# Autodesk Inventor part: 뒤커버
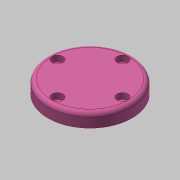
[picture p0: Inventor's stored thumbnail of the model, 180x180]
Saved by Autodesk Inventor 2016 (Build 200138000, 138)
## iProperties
Created: 2015-09
Part Number: 뒤커버
Material: 알루미늄 6061
Document SubType Name: Modeling
Designer: mduedu
Density: 1 g/cm^3
Appearance: 분홍색
Author: mduedu
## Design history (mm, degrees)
sketch "스케치1"
  geometry: L1 (0, 7.5)-(0, -7.5); L2 (0, 7.5)-(31, 7.5); L3 (31, 7.5)-(31, -2.5); L4 (31, -2.5)-(17.5, -2.5); L5 (17.5, -2.5)-(17.5, -7.5); L6 (17.5, -7.5)-(0, -7.5); 2 further points
  constraints: 12 end point, 2 parallel, 2 perpendicular, 1 coincident, 1 horizontal, 1 midpoint, 1 vertical
  dimensions: "d0" = 15 distance of L1.start L1.end; "d1" = 62 diameter of L3 L1; "d2" = 35 diameter of L5 L1; "d3" = 10 distance of L2.end L3.end
revolve "회전1" sketch "스케치1" stored, may be unused: angle "d4" = 90 deg
fillet "모깎기2" dims "d48" = 3
sketch "스케치4" dims "d49" = 48
  geometry: 3 further points
  constraints: 2 vertical alignment, 1 coincident, 2 other
hole "구멍4" sketch "스케치4" at (0, 24) diameter "d50" = 4.5; stored, may be unused: countersink angle "d54" = 90 deg, drill point angle "d56" = 118 deg; dims "d51" = 6, "d52" = 8, "d53" = 4.4, "d55" = 8
hole "구멍5" diameter "d62" = 24; stored, may be unused: countersink angle "d66" = 90 deg, drill point angle "d68" = 0 deg; dims "d60" = 10, "d61" = 10, "d63" = 6, "d64" = 4, "d65" = 2, "d67" = 8
fillet "모깎기3" dims "d69" = 3
chamfer "모따기3" distance "d43" = 1; stored, may be unused: second distance "d44" = 2, angle "d45" = 45 deg
node "솔리드1"
pattern_circular "원형 패턴1" dims angle "d58" = 360 deg
